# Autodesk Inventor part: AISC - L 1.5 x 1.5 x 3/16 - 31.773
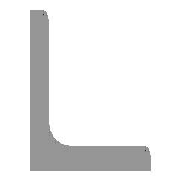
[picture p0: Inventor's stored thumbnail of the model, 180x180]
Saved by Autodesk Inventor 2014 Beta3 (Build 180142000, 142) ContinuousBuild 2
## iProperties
IsCustomPart: 1
Created: 2010-11
Part Number: AISC - L 1.5 x 1.5 x 3/16 - 31.773
Material: Steel, Mild
Description: Angle Steel
Document SubType Name: Modeling
Standard: ANSI
Designer: Beta-8540w
Standards Organization: ANSI
Language: en-US
Size Designation: L 1.5 x 1.5 x 3/16
Categories: <MemberInstance><Categories><Category DisplayName="Structural Shapes" InternalName="089c4875-fa83-4c05-b084-43b9cc11f5ed" Mnemonic="GRDR"><CategoryParameter Dis
Stock Number: L 1.5 x 1.5 x 3/16
Density: 7.86 g/cm^3
Appearance: Steel
G_L: 31.773 in
G_W: 1.500 in
G_H: 1.500 in
+AB804AD9-6BA4-4EFD-9C9E-0920120F2FE1+CUTDETAIL1: Cut
_CCFamilyMember: 5
_CCFamilyDisplayName: ANSI L (Equal angles) - Angle Steel
_FrameMemberDoc: Frame Member File
_Version: 15.0.0
_GetPNFromCC: 1
Author: Beta-8540w
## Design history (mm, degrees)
node "Start plane"
node "End plane"
sketch "Sketch"
  geometry: L1 (38.1, 0)-(0, 0); L2 (0, 0)-(0, 38.1); L3 (0, 38.1)-(2.476, 38.1); L4 (4.762, 35.814)-(4.762, 9.589); L5 (9.588, 4.763)-(35.814, 4.763); L6 (38.1, 2.477)-(38.1, 0); L7 (0, -11.041)-(0, 31.538); L8 (-11.041, 0)-(31.538, 0); L9 (0, 48.496)-(0, -20.964) reference; L10 (-20.964, 0)-(48.496, 0) reference; A1 r 4.826 centre (9.588, 9.589) between (4.762, 9.589) and (9.588, 4.763); A2 r 2.286 centre (2.476, 35.814) between (4.762, 35.814) and (2.476, 38.1); A3 r 2.286 centre (35.814, 2.477) between (38.1, 2.477) and (35.814, 4.763); 3 further points
  constraints: 16 end point, 6 point on circle, 6 point on line, 6 tangent, 4 parallel, 3 centre point, 2 collinear, 1 equal radius, 1 horizontal, 1 perpendicular
  dimensions: "d0" = 38.1 distance between parallel lines of L6 L2 (= G_H); "d1" = 38.1 distance between parallel lines of L3 L1 (= G_H); "d2" = 4.7625 distance between parallel lines of L2 L4 (= G_T); "d3" = 4.7625 distance between parallel lines of L1 L5 (= G_T); "d10" = 0 distance between parallel lines of L7 L2 (computed from ex); "d11" = 0 distance between parallel lines of L8 L1 (computed from d10); "d14" = 4.826 radius of A1 (= G_IR); "d15" = 2.286 radius of A2 (= G_ER)
extrude "Body" new body sketch "Sketch" stored distance "d4" = 807.0404 (= G_L); taper "d5" = 0 deg
node "Driven Length"
  sketch "Sketch3"
    geometry: L1 (0, 0)-(10, 0) reference
    constraints: 2 end point, 1 horizontal
  workplane "Work Plane3"
  sketch "Sketch4"
    geometry: L1 (-2, 0)-(12, 0) reference; L2 (-2, 807.04)-(12, 807.04) reference
    dimensions: "d17" = 807.0404 distance between parallel lines of L1 L2 (derived)
workplane "Work Plane4"
split "Split1"
body "Solid1"
other parameters: "G_H" = 38.1 [user parameter; used in 2 equation terms], "G_T" = 4.7625 [user parameter; used in 2 equation terms], "G_ER" = 2.286 [user parameter; used in 1 equation term], "G_IR" = 4.826 [user parameter; used in 1 equation term], "G_L" = 807.0404 (= d17) [user parameter; used in 1 equation term], "ex" = 0 [user parameter; used in 1 equation term], "G_OFFSET_START" = 0 [user parameter; used in 1 equation term], "G_OFFSET_END" = -29.72503 [user parameter; used in 1 equation term], "d12" = 0 (computed from G_OFFSET_START), "d13" = 807.0404 (= G_OFFSET_END + B_L), "B_L" = 836.76542 [user parameter; used in 1 equation term], "d16" = 90 deg, "MAS" = 0.26787 [user parameter]
